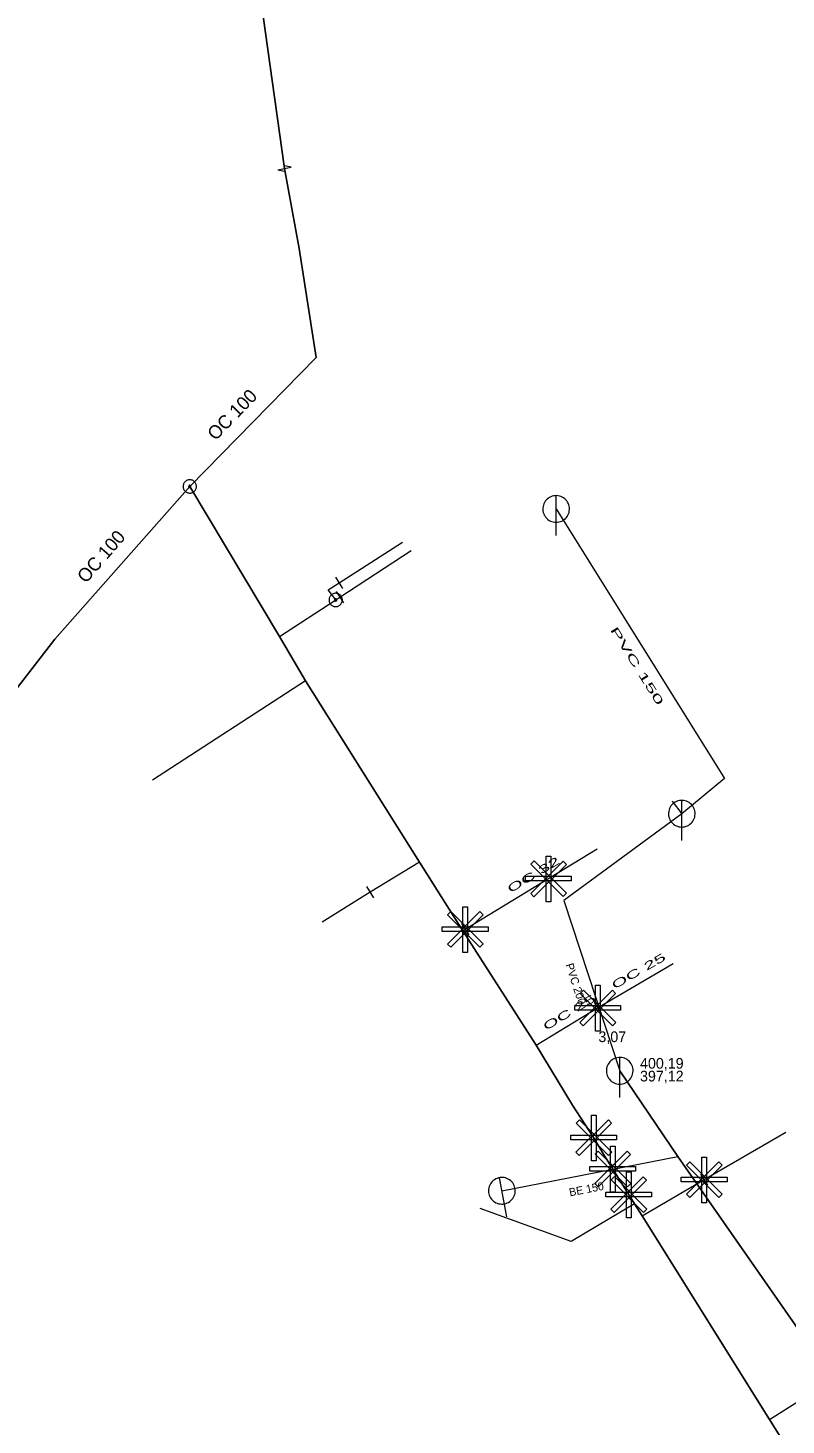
# Model space of a CAD drawing. Extents: x -809028 to -807737, y -990545 to -989489.
# Drawn here: x -808609.2 to -808552.3, y -989928.5 to -989823.8 of the extents above; entities that cross this region are included whole.
import ezdxf

# ---------------------------------------------------------------- set-up
doc = ezdxf.new("R2010")
doc.units = 0
doc.header["$LTSCALE"] = 0.32
for name, color, linetype, lineweight in [('1', 7, 'Continuous', 13), ('11', 7, 'Continuous', 13), ('12', 7, 'Continuous', 13), ('13', 7, 'Continuous', 13), ('14', 7, 'Continuous', 25), ('17', 7, 'Continuous', 25), ('22', 7, 'Continuous', 13), ('34', 7, 'Continuous', 13), ('47', 7, 'Continuous', 13)]:
    doc.layers.add(name, color=color, linetype=linetype, lineweight=lineweight)

msp = doc.modelspace()

# ---------------------------------------------------------------- linework, layer by layer
at = {"layer": '11'}
for p, q in [((-808560.826, -989881.756), (-808560.112, -989882.684)), ((-808573.609, -989910.963), (-808560.398, -989908.392))]:
    msp.add_line(p, q, dxfattribs=at)
for points in [[(-808569.538, -989859.832), (-808556.899, -989880.042), (-808560.112, -989882.684)], [(-808560.112, -989882.684), (-808568.967, -989889.182), (-808564.767, -989901.965)]]:
    msp.add_lwpolyline(points, dxfattribs=at)
at = {"layer": '12'}
for points in [[(-808569.019, -989886.235), (-808568.771, -989886.483), (-808571.2, -989888.912), (-808571.446, -989888.664)], [(-808571.438, -989886.474), (-808571.191, -989886.226), (-808568.762, -989888.655), (-808569.009, -989888.903)], [(-808570.285, -989885.871), (-808569.934, -989885.871), (-808569.934, -989889.306), (-808570.285, -989889.306)], [(-808568.401, -989887.38), (-808568.401, -989887.73), (-808571.836, -989887.73), (-808571.836, -989887.38)], [(-808576.528, -989889.665), (-808576.178, -989889.665), (-808576.178, -989893.1), (-808576.528, -989893.1)], [(-808575.262, -989890.029), (-808575.014, -989890.277), (-808577.443, -989892.706), (-808577.69, -989892.458)], [(-808577.681, -989890.268), (-808577.434, -989890.02), (-808575.005, -989892.449), (-808575.252, -989892.697)], [(-808574.644, -989891.174), (-808574.644, -989891.524), (-808578.079, -989891.524), (-808578.079, -989891.174)], [(-808565.322, -989895.918), (-808565.074, -989896.166), (-808567.503, -989898.595), (-808567.75, -989898.347)], [(-808567.741, -989896.157), (-808567.494, -989895.909), (-808565.065, -989898.338), (-808565.312, -989898.586)], [(-808566.588, -989895.554), (-808566.238, -989895.554), (-808566.238, -989898.989), (-808566.588, -989898.989)], [(-808564.704, -989897.063), (-808564.704, -989897.413), (-808568.139, -989897.413), (-808568.139, -989897.063)], [(-808566.888, -989905.284), (-808566.538, -989905.284), (-808566.538, -989908.719), (-808566.888, -989908.719)], [(-808565.622, -989905.648), (-808565.374, -989905.896), (-808567.803, -989908.325), (-808568.049, -989908.077)], [(-808568.041, -989905.887), (-808567.794, -989905.639), (-808565.365, -989908.068), (-808565.612, -989908.316)], [(-808565.004, -989906.793), (-808565.004, -989907.143), (-808568.439, -989907.143), (-808568.439, -989906.793)], [(-808564.204, -989907.991), (-808563.956, -989908.239), (-808566.385, -989910.668), (-808566.632, -989910.42)], [(-808566.623, -989908.23), (-808566.376, -989907.982), (-808563.947, -989910.411), (-808564.194, -989910.659)], [(-808565.47, -989907.627), (-808565.12, -989907.627), (-808565.12, -989911.062), (-808565.47, -989911.062)], [(-808558.598, -989908.435), (-808558.247, -989908.435), (-808558.247, -989911.87), (-808558.598, -989911.87)], [(-808563.586, -989909.136), (-808563.586, -989909.486), (-808567.021, -989909.486), (-808567.021, -989909.136)], [(-808564.265, -989909.549), (-808563.914, -989909.549), (-808563.914, -989912.984), (-808564.265, -989912.984)], [(-808557.331, -989908.799), (-808557.083, -989909.047), (-808559.512, -989911.476), (-808559.759, -989911.228)], [(-808559.75, -989909.038), (-808559.504, -989908.79), (-808557.075, -989911.219), (-808557.321, -989911.467)], [(-808562.999, -989909.913), (-808562.75, -989910.161), (-808565.179, -989912.59), (-808565.426, -989912.342)], [(-808565.418, -989910.152), (-808565.171, -989909.904), (-808562.742, -989912.333), (-808562.989, -989912.581)], [(-808556.713, -989909.944), (-808556.713, -989910.294), (-808560.149, -989910.294), (-808560.149, -989909.944)], [(-808562.38, -989911.058), (-808562.38, -989911.408), (-808565.816, -989911.408), (-808565.816, -989911.058)]]:
    msp.add_lwpolyline(points, close=True, dxfattribs=at)
at = {"layer": '13'}
for p, q in [((-808585.828, -989865.367), (-808581.061, -989862.313)), ((-808585.768, -989866.452), (-808580.42, -989862.956)), ((-808590.285, -989869.403), (-808586.079, -989866.655)), ((-808588.355, -989872.717), (-808599.829, -989880.166)), ((-808579.785, -989886.311), (-808583.48, -989888.579)), ((-808583.48, -989888.579), (-808587.086, -989890.829))]:
    msp.add_line(p, q, dxfattribs=at)
for points in [[(-808586.079, -989866.655), (-808586.636, -989865.885), (-808585.828, -989865.367)], [(-808576.531, -989891.473), (-808576.37, -989891.35), (-808566.453, -989885.323)], [(-808571.029, -989900.055), (-808566.43, -989897.239), (-808560.759, -989893.925)], [(-808563.097, -989912.848), (-808558.44, -989910.12), (-808552.294, -989906.572)], [(-808563.671, -989911.931), (-808568.407, -989914.761), (-808575.227, -989912.296)], [(-808553.532, -989928.12), (-808544.686, -989922.508), (-808538.816, -989918.699)]]:
    msp.add_lwpolyline(points, dxfattribs=at)
at = {"layer": '14', "lineweight": 13}
msp.add_line((-808586.079, -989866.655), (-808585.768, -989866.452), dxfattribs=at)
at = {"layer": '14'}
msp.add_lwpolyline([(-808564.767, -989901.965), (-808560.398, -989908.392), (-808550.052, -989923.237), (-808537.236, -989942.856)], dxfattribs=at)
at = {"layer": '17'}
for points in [[(-808593.698, -989796.145), (-808593.486, -989798.561), (-808592.215, -989812.702), (-808592.072, -989818.818), (-808591.364, -989823.94), (-808589.925, -989834.302)], [(-808589.925, -989834.302), (-808588.809, -989840.298), (-808587.546, -989848.473), (-808597.027, -989858.141)], [(-808597.027, -989858.141), (-808607.149, -989869.59), (-808610.789, -989874.309)], [(-808597.027, -989858.141), (-808590.285, -989869.403), (-808588.355, -989872.717), (-808579.785, -989886.311), (-808576.531, -989891.473), (-808571.029, -989900.055), (-808568.32, -989904.55), (-808566.73, -989906.969), (-808565.989, -989908.23), (-808563.671, -989911.931), (-808563.097, -989912.848), (-808553.532, -989928.12), (-808547.531, -989937.702), (-808538.164, -989952.659), (-808533.093, -989960.754)]]:
    msp.add_lwpolyline(points, dxfattribs=at)
at = {"layer": '22'}
for p, q in [((-808569.538, -989861.832), (-808569.537, -989858.832)), ((-808560.112, -989884.684), (-808560.111, -989881.684)), ((-808564.767, -989903.965), (-808564.766, -989900.965)), ((-808573.226, -989912.926), (-808573.799, -989909.981))]:
    msp.add_line(p, q, dxfattribs=at)
for points in [[(-808568.538, -989859.832), (-808568.543, -989859.723), (-808568.561, -989859.615), (-808568.591, -989859.509), (-808568.631, -989859.408), (-808568.683, -989859.311), (-808568.745, -989859.221), (-808568.817, -989859.138), (-808568.897, -989859.064), (-808568.985, -989858.998), (-808569.079, -989858.943), (-808569.179, -989858.898), (-808569.284, -989858.865), (-808569.391, -989858.843), (-808569.5, -989858.833), (-808569.61, -989858.835), (-808569.718, -989858.849), (-808569.825, -989858.874), (-808569.928, -989858.911), (-808570.026, -989858.96), (-808570.118, -989859.018), (-808570.204, -989859.087), (-808570.281, -989859.164), (-808570.35, -989859.25), (-808570.409, -989859.342), (-808570.457, -989859.44), (-808570.494, -989859.543), (-808570.52, -989859.65), (-808570.534, -989859.758), (-808570.537, -989859.868), (-808570.527, -989859.977), (-808570.506, -989860.084), (-808570.472, -989860.188), (-808570.428, -989860.288), (-808570.373, -989860.383), (-808570.307, -989860.471), (-808570.233, -989860.551), (-808570.15, -989860.623), (-808570.06, -989860.685), (-808569.964, -989860.737), (-808569.862, -989860.778), (-808569.757, -989860.808), (-808569.649, -989860.826), (-808569.539, -989860.832), (-808569.43, -989860.826), (-808569.322, -989860.808), (-808569.217, -989860.779), (-808569.115, -989860.738), (-808569.018, -989860.686), (-808568.928, -989860.624), (-808568.845, -989860.553), (-808568.77, -989860.473), (-808568.705, -989860.385), (-808568.649, -989860.291), (-808568.605, -989860.191), (-808568.571, -989860.087), (-808568.549, -989859.979), (-808568.539, -989859.87)], [(-808559.112, -989882.684), (-808559.117, -989882.575), (-808559.135, -989882.467), (-808559.165, -989882.361), (-808559.205, -989882.26), (-808559.257, -989882.163), (-808559.319, -989882.073), (-808559.391, -989881.99), (-808559.471, -989881.916), (-808559.559, -989881.85), (-808559.653, -989881.795), (-808559.753, -989881.75), (-808559.858, -989881.717), (-808559.965, -989881.695), (-808560.074, -989881.685), (-808560.184, -989881.687), (-808560.292, -989881.701), (-808560.399, -989881.726), (-808560.502, -989881.763), (-808560.6, -989881.812), (-808560.692, -989881.87), (-808560.778, -989881.939), (-808560.855, -989882.016), (-808560.924, -989882.102), (-808560.983, -989882.194), (-808561.031, -989882.292), (-808561.068, -989882.395), (-808561.094, -989882.502), (-808561.108, -989882.61), (-808561.111, -989882.72), (-808561.101, -989882.829), (-808561.08, -989882.936), (-808561.046, -989883.04), (-808561.002, -989883.14), (-808560.947, -989883.235), (-808560.881, -989883.323), (-808560.807, -989883.403), (-808560.724, -989883.475), (-808560.634, -989883.537), (-808560.538, -989883.589), (-808560.436, -989883.63), (-808560.331, -989883.66), (-808560.223, -989883.678), (-808560.113, -989883.684), (-808560.004, -989883.678), (-808559.896, -989883.66), (-808559.791, -989883.631), (-808559.689, -989883.59), (-808559.592, -989883.538), (-808559.502, -989883.476), (-808559.419, -989883.405), (-808559.344, -989883.325), (-808559.279, -989883.237), (-808559.223, -989883.143), (-808559.179, -989883.043), (-808559.145, -989882.939), (-808559.123, -989882.831), (-808559.113, -989882.722)], [(-808563.767, -989901.965), (-808563.772, -989901.856), (-808563.79, -989901.748), (-808563.82, -989901.642), (-808563.86, -989901.541), (-808563.912, -989901.444), (-808563.974, -989901.354), (-808564.046, -989901.271), (-808564.126, -989901.197), (-808564.214, -989901.131), (-808564.308, -989901.076), (-808564.408, -989901.031), (-808564.513, -989900.998), (-808564.62, -989900.976), (-808564.729, -989900.966), (-808564.839, -989900.968), (-808564.947, -989900.982), (-808565.054, -989901.007), (-808565.157, -989901.044), (-808565.255, -989901.093), (-808565.347, -989901.151), (-808565.433, -989901.22), (-808565.51, -989901.297), (-808565.579, -989901.383), (-808565.638, -989901.475), (-808565.686, -989901.573), (-808565.723, -989901.676), (-808565.749, -989901.783), (-808565.763, -989901.891), (-808565.766, -989902.001), (-808565.756, -989902.11), (-808565.735, -989902.217), (-808565.701, -989902.321), (-808565.657, -989902.421), (-808565.602, -989902.516), (-808565.536, -989902.604), (-808565.462, -989902.684), (-808565.379, -989902.756), (-808565.289, -989902.818), (-808565.193, -989902.87), (-808565.091, -989902.911), (-808564.986, -989902.941), (-808564.878, -989902.959), (-808564.768, -989902.965), (-808564.659, -989902.959), (-808564.551, -989902.941), (-808564.446, -989902.912), (-808564.344, -989902.871), (-808564.247, -989902.819), (-808564.157, -989902.757), (-808564.074, -989902.686), (-808563.999, -989902.606), (-808563.934, -989902.518), (-808563.878, -989902.424), (-808563.834, -989902.324), (-808563.8, -989902.22), (-808563.778, -989902.112), (-808563.768, -989902.003)], [(-808572.627, -989910.772), (-808572.654, -989910.666), (-808572.692, -989910.564), (-808572.742, -989910.465), (-808572.8, -989910.374), (-808572.87, -989910.288), (-808572.948, -989910.212), (-808573.034, -989910.144), (-808573.127, -989910.087), (-808573.226, -989910.039), (-808573.329, -989910.003), (-808573.435, -989909.978), (-808573.545, -989909.965), (-808573.654, -989909.964), (-808573.763, -989909.975), (-808573.871, -989909.998), (-808573.974, -989910.033), (-808574.074, -989910.078), (-808574.168, -989910.134), (-808574.255, -989910.2), (-808574.334, -989910.275), (-808574.405, -989910.359), (-808574.466, -989910.449), (-808574.518, -989910.547), (-808574.558, -989910.649), (-808574.586, -989910.754), (-808574.603, -989910.862), (-808574.608, -989910.972), (-808574.601, -989911.081), (-808574.582, -989911.189), (-808574.551, -989911.294), (-808574.51, -989911.395), (-808574.457, -989911.491), (-808574.395, -989911.581), (-808574.323, -989911.663), (-808574.241, -989911.737), (-808574.153, -989911.802), (-808574.058, -989911.856), (-808573.958, -989911.9), (-808573.854, -989911.933), (-808573.746, -989911.953), (-808573.637, -989911.963), (-808573.527, -989911.96), (-808573.418, -989911.945), (-808573.313, -989911.918), (-808573.21, -989911.88), (-808573.112, -989911.831), (-808573.02, -989911.772), (-808572.935, -989911.702), (-808572.858, -989911.624), (-808572.79, -989911.538), (-808572.732, -989911.445), (-808572.685, -989911.347), (-808572.648, -989911.244), (-808572.624, -989911.137), (-808572.611, -989911.029), (-808572.61, -989910.918), (-808572.621, -989910.809)]]:
    msp.add_lwpolyline(points, close=True, dxfattribs=at)
at = {"layer": '34'}
for p, q in [((-808586.098, -989864.946), (-808585.558, -989865.788)), ((-808586.041, -989866.033), (-808585.494, -989866.87)), ((-808583.214, -989889.002), (-808583.744, -989888.154)), ((-808576.643, -989890.931), (-808576.097, -989891.769)), ((-808566.691, -989896.812), (-808566.169, -989897.665)), ((-808558.699, -989909.692), (-808558.181, -989910.547))]:
    msp.add_line(p, q, dxfattribs=at)
at = {"layer": '47'}
msp.add_line((-808590.425, -989834.399), (-808589.925, -989834.503), dxfattribs=at)
msp.add_lwpolyline([(-808590.425, -989834.399), (-808589.424, -989834.204), (-808589.924, -989834.101)], dxfattribs=at)
for points in [[(-808596.732, -989857.736), (-808596.776, -989857.708), (-808596.823, -989857.684), (-808596.872, -989857.666), (-808596.922, -989857.652), (-808596.974, -989857.643), (-808597.027, -989857.641), (-808597.078, -989857.644), (-808597.13, -989857.652), (-808597.18, -989857.665), (-808597.23, -989857.684), (-808597.277, -989857.707), (-808597.32, -989857.737), (-808597.361, -989857.769), (-808597.398, -989857.806), (-808597.431, -989857.846), (-808597.459, -989857.89), (-808597.483, -989857.937), (-808597.502, -989857.986), (-808597.515, -989858.036), (-808597.524, -989858.088), (-808597.526, -989858.141), (-808597.524, -989858.193), (-808597.515, -989858.245), (-808597.503, -989858.295), (-808597.483, -989858.344), (-808597.46, -989858.391), (-808597.431, -989858.435), (-808597.398, -989858.475), (-808597.361, -989858.512), (-808597.321, -989858.545), (-808597.277, -989858.573), (-808597.23, -989858.597), (-808597.181, -989858.617), (-808597.131, -989858.629), (-808597.079, -989858.638), (-808597.027, -989858.641), (-808596.974, -989858.638), (-808596.923, -989858.63), (-808596.872, -989858.617), (-808596.823, -989858.597), (-808596.776, -989858.574), (-808596.733, -989858.546), (-808596.692, -989858.512), (-808596.655, -989858.475), (-808596.622, -989858.435), (-808596.594, -989858.391), (-808596.57, -989858.344), (-808596.551, -989858.296), (-808596.538, -989858.245), (-808596.529, -989858.193), (-808596.526, -989858.141), (-808596.529, -989858.089), (-808596.537, -989858.038), (-808596.551, -989857.987), (-808596.57, -989857.937), (-808596.593, -989857.89), (-808596.622, -989857.848), (-808596.655, -989857.806), (-808596.692, -989857.769)], [(-808596.978, -989858.074), (-808596.986, -989858.069), (-808596.993, -989858.066), (-808597.001, -989858.063), (-808597.009, -989858.06), (-808597.018, -989858.059), (-808597.026, -989858.059), (-808597.035, -989858.059), (-808597.043, -989858.06), (-808597.052, -989858.063), (-808597.06, -989858.066), (-808597.068, -989858.07), (-808597.075, -989858.074), (-808597.081, -989858.08), (-808597.088, -989858.085), (-808597.093, -989858.092), (-808597.098, -989858.1), (-808597.101, -989858.107), (-808597.104, -989858.115), (-808597.107, -989858.123), (-808597.108, -989858.132), (-808597.108, -989858.14), (-808597.108, -989858.149), (-808597.107, -989858.157), (-808597.105, -989858.166), (-808597.101, -989858.174), (-808597.097, -989858.182), (-808597.093, -989858.189), (-808597.087, -989858.195), (-808597.082, -989858.202), (-808597.075, -989858.207), (-808597.067, -989858.212), (-808597.06, -989858.215), (-808597.052, -989858.218), (-808597.044, -989858.221), (-808597.035, -989858.222), (-808597.027, -989858.223), (-808597.018, -989858.222), (-808597.01, -989858.221), (-808597.001, -989858.219), (-808596.993, -989858.215), (-808596.985, -989858.211), (-808596.978, -989858.207), (-808596.972, -989858.201), (-808596.965, -989858.196), (-808596.96, -989858.189), (-808596.955, -989858.181), (-808596.952, -989858.174), (-808596.949, -989858.166), (-808596.946, -989858.158), (-808596.945, -989858.149), (-808596.944, -989858.141), (-808596.945, -989858.132), (-808596.946, -989858.124), (-808596.949, -989858.115), (-808596.952, -989858.107), (-808596.956, -989858.099), (-808596.96, -989858.092), (-808596.966, -989858.086), (-808596.971, -989858.079)], [(-808585.66, -989866.381), (-808585.691, -989866.339), (-808585.726, -989866.3), (-808585.765, -989866.266), (-808585.807, -989866.235), (-808585.853, -989866.208), (-808585.901, -989866.187), (-808585.951, -989866.172), (-808586.002, -989866.161), (-808586.053, -989866.155), (-808586.106, -989866.155), (-808586.159, -989866.161), (-808586.209, -989866.173), (-808586.259, -989866.188), (-808586.307, -989866.21), (-808586.352, -989866.236), (-808586.394, -989866.267), (-808586.433, -989866.302), (-808586.468, -989866.342), (-808586.498, -989866.383), (-808586.525, -989866.429), (-808586.546, -989866.477), (-808586.562, -989866.527), (-808586.573, -989866.578), (-808586.578, -989866.63), (-808586.578, -989866.682), (-808586.572, -989866.735), (-808586.561, -989866.786), (-808586.545, -989866.835), (-808586.523, -989866.883), (-808586.497, -989866.928), (-808586.466, -989866.97), (-808586.431, -989867.009), (-808586.392, -989867.045), (-808586.35, -989867.074), (-808586.304, -989867.101), (-808586.257, -989867.122), (-808586.207, -989867.138), (-808586.155, -989867.149), (-808586.103, -989867.154), (-808586.051, -989867.154), (-808585.998, -989867.148), (-808585.948, -989867.138), (-808585.898, -989867.121), (-808585.85, -989867.099), (-808585.805, -989867.073), (-808585.763, -989867.042), (-808585.724, -989867.007), (-808585.689, -989866.969), (-808585.659, -989866.926), (-808585.632, -989866.88), (-808585.611, -989866.833), (-808585.595, -989866.783), (-808585.585, -989866.732), (-808585.579, -989866.68), (-808585.579, -989866.627), (-808585.585, -989866.574), (-808585.596, -989866.524), (-808585.612, -989866.474), (-808585.634, -989866.426)], [(-808586.01, -989866.61), (-808586.015, -989866.602), (-808586.021, -989866.597), (-808586.027, -989866.591), (-808586.034, -989866.586), (-808586.041, -989866.581), (-808586.05, -989866.578), (-808586.058, -989866.575), (-808586.066, -989866.573), (-808586.074, -989866.573), (-808586.083, -989866.573), (-808586.092, -989866.574), (-808586.1, -989866.576), (-808586.108, -989866.578), (-808586.116, -989866.581), (-808586.123, -989866.586), (-808586.131, -989866.591), (-808586.136, -989866.597), (-808586.142, -989866.603), (-808586.147, -989866.61), (-808586.152, -989866.617), (-808586.155, -989866.626), (-808586.158, -989866.634), (-808586.16, -989866.642), (-808586.161, -989866.651), (-808586.16, -989866.659), (-808586.159, -989866.668), (-808586.157, -989866.676), (-808586.155, -989866.684), (-808586.152, -989866.692), (-808586.147, -989866.699), (-808586.142, -989866.707), (-808586.136, -989866.712), (-808586.13, -989866.718), (-808586.123, -989866.723), (-808586.116, -989866.728), (-808586.108, -989866.731), (-808586.099, -989866.734), (-808586.091, -989866.736), (-808586.082, -989866.737), (-808586.074, -989866.736), (-808586.065, -989866.735), (-808586.057, -989866.733), (-808586.049, -989866.731), (-808586.041, -989866.728), (-808586.034, -989866.723), (-808586.026, -989866.718), (-808586.021, -989866.712), (-808586.015, -989866.706), (-808586.01, -989866.699), (-808586.005, -989866.692), (-808586.002, -989866.684), (-808585.999, -989866.675), (-808585.997, -989866.667), (-808585.997, -989866.659), (-808585.997, -989866.65), (-808585.998, -989866.641), (-808586, -989866.633), (-808586.002, -989866.625), (-808586.005, -989866.617)]]:
    msp.add_lwpolyline(points, close=True, dxfattribs=at)

# ---------------------------------------------------------------- texts
at = {"layer": '1'}
for s, height, rotation, p in [('OC 100', 1, 46, (-808595.09, -989854.759)), ('OC 100', 1, 49, (-808604.813, -989865.459)), ('PVC 200 ', 0.6, 288, (-808568.844, -989894.012)), ('BE 150', 0.6, 11, (-808568.504, -989911.386))]:
    msp.add_text(s, height=height, rotation=rotation, dxfattribs=at).set_placement(p)
for s, rotation, width, p in [('PVC 150 ', 302, 2.1, (-808565.511, -989868.894)), ('OC 32 ', 31, 1.9, (-808572.974, -989888.652)), ('OC 25 ', 30, 1.95, (-808565.162, -989895.872)), ('OC 25 ', 31, 1.9, (-808570.291, -989898.968))]:
    msp.add_text(s, height=0.6, rotation=rotation, dxfattribs=dict(at, width=width)).set_placement(p)
msp.add_text('3,07', height=0.8, dxfattribs=at).set_placement((-808566.367, -989899.813))
at = {"layer": '14'}
for s, p in [('400,19', (-808563.246, -989901.805)), ('397,12', (-808563.246, -989902.765))]:
    msp.add_text(s, height=0.8, dxfattribs=at).set_placement(p)

doc.saveas('drawing.dxf')
